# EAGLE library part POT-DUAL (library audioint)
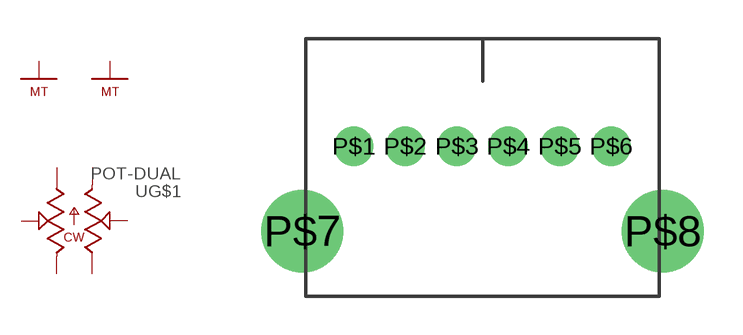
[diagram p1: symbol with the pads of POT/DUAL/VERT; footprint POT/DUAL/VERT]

Designator prefix -; gates G$1=POT-DUAL G$2=MECHANICAL G$3=MECHANICAL

## POT-DUALPANASONIC  [POT/DUAL/VERT]
P$1  G$1:A1  pas
P$2  G$1:E  pas
P$3  G$1:S  pas
P$4  G$1:A  pas
P$5  G$1:E1  pas
P$6  G$1:S1  pas
P$7  G$2:MT  pas
P$8  G$3:MT  pas

## Footprint POT/DUAL/VERT (pad centres in mm)
drill 0.914 pad 1.524 round: P$1 -5,0; P$2 -3,0; P$3 -1,0; P$4 1,0; P$5 3,0; P$6 5,0
drill 2.108 pad 3.2 round: P$7 -7,-3.3; P$8 7,-3.3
